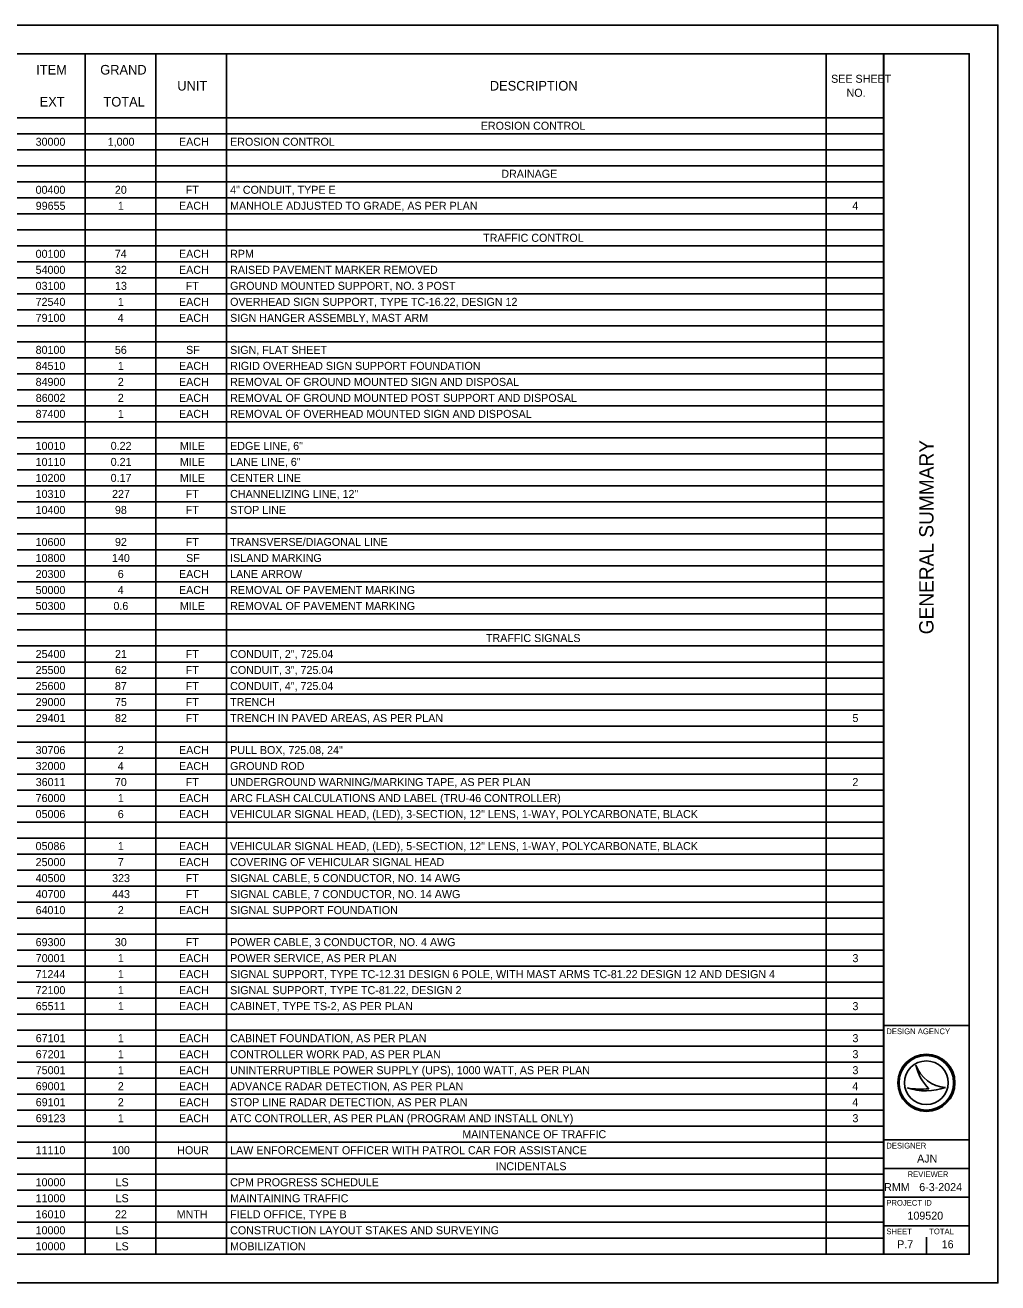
# Model space of a CAD drawing. Extents: x 0 to 34, y 0 to 22.
# Drawn here: x 16.99 to 34, y 0 to 22 of the extents above; entities that cross this region are included whole.
import ezdxf

# ---------------------------------------------------------------- set-up
doc = ezdxf.new("R2010")
doc.units = 0
for name, color, linetype in [('Default', 7, 'Continuous'), ('SH_Border', 7, 'Continuous'), ('SH_Cut_Line', 7, 'Continuous'), ('SH_Data', 7, 'Continuous')]:
    doc.layers.add(name, color=color, linetype=linetype)

msp = doc.modelspace()

# ---------------------------------------------------------------- linework, layer by layer
at = {"layer": 'Default'}
for p, q in [((1.5, 21.5), (32.004, 21.5)), ((18.036, 21.5), (18.036, 0.5)), ((19.272, 21.5), (19.272, 0.5)), ((20.507, 21.5), (20.507, 0.5)), ((30.999, 21.5), (30.999, 0.5)), ((32.004, 21.5), (32.004, 0.5)), ((1.5, 20.38), (32.004, 20.38)), ((1.5, 20.1), (32.004, 20.1)), ((1.5, 19.82), (32.004, 19.82)), ((1.5, 19.54), (32.004, 19.54)), ((1.5, 19.26), (32.004, 19.26)), ((1.5, 18.98), (32.004, 18.98)), ((1.5, 18.7), (32.004, 18.7)), ((1.5, 18.42), (32.004, 18.42)), ((1.5, 18.14), (32.004, 18.14)), ((1.5, 17.86), (32.004, 17.86)), ((1.5, 17.58), (32.004, 17.58)), ((1.5, 17.3), (32.004, 17.3)), ((1.5, 17.02), (32.004, 17.02)), ((1.5, 16.74), (32.004, 16.74)), ((1.5, 16.46), (32.004, 16.46)), ((1.5, 16.18), (32.004, 16.18)), ((1.5, 15.9), (32.004, 15.9)), ((1.5, 15.62), (32.004, 15.62)), ((1.5, 15.34), (32.004, 15.34)), ((1.5, 15.06), (32.004, 15.06)), ((1.5, 14.78), (32.004, 14.78)), ((1.5, 14.5), (32.004, 14.5)), ((1.5, 14.22), (32.004, 14.22)), ((1.5, 13.94), (32.004, 13.94)), ((1.5, 13.66), (32.004, 13.66)), ((1.5, 13.38), (32.004, 13.38)), ((1.5, 13.1), (32.004, 13.1)), ((1.5, 12.82), (32.004, 12.82)), ((1.5, 12.54), (32.004, 12.54)), ((1.5, 12.26), (32.004, 12.26)), ((1.5, 11.98), (32.004, 11.98)), ((1.5, 11.7), (32.004, 11.7)), ((1.5, 11.42), (32.004, 11.42)), ((1.5, 11.14), (32.004, 11.14)), ((1.5, 10.86), (32.004, 10.86)), ((1.5, 10.58), (32.004, 10.58)), ((1.5, 10.3), (32.004, 10.3)), ((1.5, 10.02), (32.004, 10.02)), ((1.5, 9.74), (32.004, 9.74)), ((1.5, 9.46), (32.004, 9.46)), ((1.5, 9.18), (32.004, 9.18)), ((1.5, 8.9), (32.004, 8.9)), ((1.5, 8.62), (32.004, 8.62)), ((1.5, 8.34), (32.004, 8.34)), ((1.5, 8.06), (32.004, 8.06)), ((1.5, 7.78), (32.004, 7.78)), ((1.5, 7.5), (32.004, 7.5)), ((1.5, 7.22), (32.004, 7.22)), ((1.5, 6.94), (32.004, 6.94)), ((1.5, 6.66), (32.004, 6.66)), ((1.5, 6.38), (32.004, 6.38)), ((1.5, 6.1), (32.004, 6.1)), ((1.5, 5.82), (32.004, 5.82)), ((1.5, 5.54), (32.004, 5.54)), ((1.5, 5.26), (32.004, 5.26)), ((1.5, 4.98), (32.004, 4.98)), ((1.5, 4.7), (32.004, 4.7)), ((1.5, 4.42), (32.004, 4.42)), ((1.5, 4.14), (32.004, 4.14)), ((1.5, 3.86), (32.004, 3.86)), ((1.5, 3.58), (32.004, 3.58)), ((1.5, 3.3), (32.004, 3.3)), ((1.5, 3.02), (32.004, 3.02)), ((1.5, 2.74), (32.004, 2.74)), ((1.5, 2.46), (32.004, 2.46)), ((1.5, 2.18), (32.004, 2.18)), ((1.5, 1.9), (32.004, 1.9)), ((1.5, 1.62), (32.004, 1.62)), ((1.5, 1.34), (32.004, 1.34)), ((1.5, 1.06), (32.004, 1.06)), ((1.5, 0.78), (32.004, 0.78)), ((1.5, 0.5), (32.004, 0.5))]:
    msp.add_line(p, q, dxfattribs=at)
at = {"layer": 'SH_Border'}
for p, q in [((32, 0.5), (32, 21.5)), ((32, 4.5), (33.5, 4.5)), ((32, 2.5), (33.5, 2.5)), ((32, 2), (33.5, 2)), ((32, 1.5), (33.5, 1.5)), ((32, 1), (33.5, 1))]:
    msp.add_line(p, q, dxfattribs=at)
msp.add_lwpolyline([(1.5, 21.5), (33.5, 21.5), (33.5, 0.5), (1.5, 0.5)], close=True, dxfattribs=at)
at = {"layer": 'SH_Cut_Line'}
msp.add_lwpolyline([(0, 0), (34, 0), (34, 22), (0, 22)], close=True, dxfattribs=at)
at = {"layer": 'SH_Data'}
for p, q in [((32.567, 3.81), (32.567, 3.81)), ((32.417, 3.41), (32.417, 3.41)), ((32.75, 3.5), (32.75, 3.5)), ((33.087, 3.419), (33.087, 3.419)), ((32.375, 0.675), (32.375, 0.675)), ((32.75, 0.5), (32.75, 0.8))]:
    msp.add_line(p, q, dxfattribs=at)
for radius in [0.5, 0.477, 0.477, 0.382]:
    msp.add_circle((32.75, 3.5), radius, dxfattribs=at)
for centre, radius, start, end in [((33.116, 3.998), 0.58, 198.9257, 198.9319), ((33.347, 3.97), 0.796, 191.6379, 191.6421), ((33.116, 3.998), 0.58, 198.9319, 267.1657), ((33.347, 3.97), 0.796, 191.6421, 226.0947), ((32.739, 4.37), 1.013, 251.4576, 290.0832), ((32.648, 4.654), 1.266, 259.4964, 259.4995), ((32.739, 4.37), 1.013, 251.4527, 251.4576), ((32.648, 4.654), 1.266, 259.4995, 276.6672)]:
    msp.add_arc(centre, radius, start, end, dxfattribs=at)

# ---------------------------------------------------------------- texts
at = {"layer": 'Default'}
for s, height, p in [('ITEM', 0.168, (17.181, 21.136)), ('GRAND', 0.168, (18.301, 21.136)), ('SEE SHEET ', 0.14, (31.084, 20.992)), ('UNIT', 0.168, (19.649, 20.856)), ('DESCRIPTION', 0.168, (25.115, 20.856)), ('EXT', 0.168, (17.242, 20.576)), ('TOTAL', 0.168, (18.357, 20.576)), ('NO.', 0.14, (31.354, 20.747)), ('EROSION CONTROL', 0.14, (24.957, 20.17)), ('30000', 0.14, (17.171, 19.89)), ('1,000', 0.14, (18.432, 19.89)), ('EACH', 0.14, (19.679, 19.89)), ('EROSION CONTROL', 0.14, (20.573, 19.89)), ('DRAINAGE', 0.14, (25.316, 19.33)), ('00400', 0.14, (17.171, 19.05)), ('20', 0.14, (18.557, 19.05)), ('FT', 0.14, (19.796, 19.05)), ('4" CONDUIT, TYPE E', 0.14, (20.573, 19.05)), ('99655', 0.14, (17.173, 18.77)), ('1', 0.14, (18.609, 18.77)), ('EACH', 0.14, (19.679, 18.77)), ('MANHOLE ADJUSTED TO GRADE, AS PER PLAN', 0.14, (20.573, 18.77)), ('4', 0.14, (31.454, 18.77)), ('TRAFFIC CONTROL', 0.14, (24.998, 18.21)), ('00100', 0.14, (17.171, 17.93)), ('74', 0.14, (18.556, 17.93)), ('EACH', 0.14, (19.679, 17.93)), ('RPM', 0.14, (20.573, 17.93)), ('54000', 0.14, (17.171, 17.65)), ('32', 0.14, (18.559, 17.65)), ('EACH', 0.14, (19.679, 17.65)), ('RAISED PAVEMENT MARKER REMOVED', 0.14, (20.573, 17.65)), ('03100', 0.14, (17.171, 17.37)), ('13', 0.14, (18.56, 17.37)), ('FT', 0.14, (19.796, 17.37)), ('GROUND MOUNTED SUPPORT, NO. 3 POST', 0.14, (20.573, 17.37)), ('72540', 0.14, (17.171, 17.09)), ('1', 0.14, (18.609, 17.09)), ('EACH', 0.14, (19.679, 17.09)), ('OVERHEAD SIGN SUPPORT, TYPE TC-16.22, DESIGN 12', 0.14, (20.573, 17.09)), ('79100', 0.14, (17.171, 16.81)), ('4', 0.14, (18.607, 16.81)), ('EACH', 0.14, (19.679, 16.81)), ('SIGN HANGER ASSEMBLY, MAST ARM', 0.14, (20.573, 16.81)), ('80100', 0.14, (17.171, 16.25)), ('56', 0.14, (18.557, 16.25)), ('SF', 0.14, (19.803, 16.25)), ('SIGN, FLAT SHEET', 0.14, (20.573, 16.25)), ('84510', 0.14, (17.171, 15.97)), ('1', 0.14, (18.609, 15.97)), ('EACH', 0.14, (19.679, 15.97)), ('RIGID OVERHEAD SIGN SUPPORT FOUNDATION', 0.14, (20.573, 15.97)), ('84900', 0.14, (17.171, 15.69)), ('2', 0.14, (18.609, 15.69)), ('EACH', 0.14, (19.679, 15.69)), ('REMOVAL OF GROUND MOUNTED SIGN AND DISPOSAL', 0.14, (20.573, 15.69)), ('86002', 0.14, (17.173, 15.41)), ('2', 0.14, (18.609, 15.41)), ('EACH', 0.14, (19.679, 15.41)), ('REMOVAL OF GROUND MOUNTED POST SUPPORT AND DISPOSAL', 0.14, (20.573, 15.41)), ('87400', 0.14, (17.171, 15.13)), ('1', 0.14, (18.609, 15.13)), ('EACH', 0.14, (19.679, 15.13)), ('REMOVAL OF OVERHEAD MOUNTED SIGN AND DISPOSAL', 0.14, (20.573, 15.13)), ('10010', 0.14, (17.171, 14.57)), ('0.22', 0.14, (18.484, 14.57)), ('MILE', 0.14, (19.695, 14.57)), ('EDGE LINE, 6"', 0.14, (20.573, 14.57)), ('10110', 0.14, (17.171, 14.29)), ('0.21', 0.14, (18.484, 14.29)), ('MILE', 0.14, (19.695, 14.29)), ('LANE LINE, 6"', 0.14, (20.573, 14.29)), ('10200', 0.14, (17.171, 14.01)), ('0.17', 0.14, (18.483, 14.01)), ('MILE', 0.14, (19.695, 14.01)), ('CENTER LINE', 0.14, (20.573, 14.01)), ('10310', 0.14, (17.171, 13.73)), ('227', 0.14, (18.508, 13.73)), ('FT', 0.14, (19.796, 13.73)), ('CHANNELIZING LINE, 12"', 0.14, (20.573, 13.73)), ('10400', 0.14, (17.171, 13.45)), ('98', 0.14, (18.558, 13.45)), ('FT', 0.14, (19.796, 13.45)), ('STOP LINE', 0.14, (20.573, 13.45)), ('10600', 0.14, (17.171, 12.89)), ('92', 0.14, (18.559, 12.89)), ('FT', 0.14, (19.796, 12.89)), ('TRANSVERSE/DIAGONAL LINE', 0.14, (20.573, 12.89)), ('10800', 0.14, (17.171, 12.61)), ('140', 0.14, (18.507, 12.61)), ('SF', 0.14, (19.803, 12.61)), ('ISLAND MARKING', 0.14, (20.573, 12.61)), ('20300', 0.14, (17.171, 12.33)), ('6', 0.14, (18.608, 12.33)), ('EACH', 0.14, (19.679, 12.33)), ('LANE ARROW', 0.14, (20.573, 12.33)), ('50000', 0.14, (17.171, 12.05)), ('4', 0.14, (18.607, 12.05)), ('EACH', 0.14, (19.679, 12.05)), ('REMOVAL OF PAVEMENT MARKING', 0.14, (20.573, 12.05)), ('50300', 0.14, (17.171, 11.77)), ('0.6', 0.14, (18.532, 11.77)), ('MILE', 0.14, (19.695, 11.77)), ('REMOVAL OF PAVEMENT MARKING', 0.14, (20.573, 11.77)), ('TRAFFIC SIGNALS', 0.14, (25.047, 11.21)), ('25400', 0.14, (17.171, 10.93)), ('21', 0.14, (18.559, 10.93)), ('FT', 0.14, (19.796, 10.93)), ('CONDUIT, 2", 725.04', 0.14, (20.573, 10.93)), ('25500', 0.14, (17.171, 10.65)), ('62', 0.14, (18.559, 10.65)), ('FT', 0.14, (19.796, 10.65)), ('CONDUIT, 3", 725.04', 0.14, (20.573, 10.65)), ('25600', 0.14, (17.171, 10.37)), ('87', 0.14, (18.558, 10.37)), ('FT', 0.14, (19.796, 10.37)), ('CONDUIT, 4", 725.04', 0.14, (20.573, 10.37)), ('29000', 0.14, (17.171, 10.09)), ('75', 0.14, (18.559, 10.09)), ('FT', 0.14, (19.796, 10.09)), ('TRENCH', 0.14, (20.573, 10.09)), ('29401', 0.14, (17.173, 9.81)), ('82', 0.14, (18.559, 9.81)), ('FT', 0.14, (19.796, 9.81)), ('TRENCH IN PAVED AREAS, AS PER PLAN', 0.14, (20.573, 9.81)), ('5', 0.14, (31.457, 9.81)), ('30706', 0.14, (17.171, 9.25)), ('2', 0.14, (18.609, 9.25)), ('EACH', 0.14, (19.679, 9.25)), ('PULL BOX, 725.08, 24"', 0.14, (20.573, 9.25)), ('32000', 0.14, (17.171, 8.97)), ('4', 0.14, (18.607, 8.97)), ('EACH', 0.14, (19.679, 8.97)), ('GROUND ROD', 0.14, (20.573, 8.97)), ('36011', 0.14, (17.173, 8.69)), ('70', 0.14, (18.557, 8.69)), ('FT', 0.14, (19.796, 8.69)), ('UNDERGROUND WARNING/MARKING TAPE, AS PER PLAN', 0.14, (20.573, 8.69)), ('2', 0.14, (31.456, 8.69)), ('76000', 0.14, (17.171, 8.41)), ('1', 0.14, (18.609, 8.41)), ('EACH', 0.14, (19.679, 8.41)), ('ARC FLASH CALCULATIONS AND LABEL (TRU-46 CONTROLLER)', 0.14, (20.573, 8.41)), ('05006', 0.14, (17.171, 8.13)), ('6', 0.14, (18.608, 8.13)), ('EACH', 0.14, (19.679, 8.13)), ('VEHICULAR SIGNAL HEAD, (LED), 3-SECTION, 12" LENS, 1-WAY, POLYCARBONATE, BLACK', 0.14, (20.573, 8.13)), ('05086', 0.14, (17.171, 7.57)), ('1', 0.14, (18.609, 7.57)), ('EACH', 0.14, (19.679, 7.57)), ('VEHICULAR SIGNAL HEAD, (LED), 5-SECTION, 12" LENS, 1-WAY, POLYCARBONATE, BLACK', 0.14, (20.573, 7.57)), ('25000', 0.14, (17.171, 7.29)), ('7', 0.14, (18.608, 7.29)), ('EACH', 0.14, (19.679, 7.29)), ('COVERING OF VEHICULAR SIGNAL HEAD', 0.14, (20.573, 7.29)), ('40500', 0.14, (17.171, 7.01)), ('323', 0.14, (18.509, 7.01)), ('FT', 0.14, (19.796, 7.01)), ('SIGNAL CABLE, 5 CONDUCTOR, NO. 14 AWG', 0.14, (20.573, 7.01)), ('40700', 0.14, (17.171, 6.73)), ('443', 0.14, (18.509, 6.73)), ('FT', 0.14, (19.796, 6.73)), ('SIGNAL CABLE, 7 CONDUCTOR, NO. 14 AWG', 0.14, (20.573, 6.73)), ('64010', 0.14, (17.171, 6.45)), ('2', 0.14, (18.609, 6.45)), ('EACH', 0.14, (19.679, 6.45)), ('SIGNAL SUPPORT FOUNDATION', 0.14, (20.573, 6.45)), ('69300', 0.14, (17.171, 5.89)), ('30', 0.14, (18.557, 5.89)), ('FT', 0.14, (19.796, 5.89)), ('POWER CABLE, 3 CONDUCTOR, NO. 4 AWG', 0.14, (20.573, 5.89)), ('70001', 0.14, (17.173, 5.61)), ('1', 0.14, (18.609, 5.61)), ('EACH', 0.14, (19.679, 5.61)), ('POWER SERVICE, AS PER PLAN', 0.14, (20.573, 5.61)), ('3', 0.14, (31.457, 5.61)), ('71244', 0.14, (17.17, 5.33)), ('1', 0.14, (18.609, 5.33)), ('EACH', 0.14, (19.679, 5.33)), ('SIGNAL SUPPORT, TYPE TC-12.31 DESIGN 6 POLE, WITH MAST ARMS TC-81.22 DESIGN 12 AND DESIGN 4', 0.14, (20.573, 5.33)), ('72100', 0.14, (17.171, 5.05)), ('1', 0.14, (18.609, 5.05)), ('EACH', 0.14, (19.679, 5.05)), ('SIGNAL SUPPORT, TYPE TC-81.22, DESIGN 2', 0.14, (20.573, 5.05)), ('65511', 0.14, (17.173, 4.77)), ('1', 0.14, (18.609, 4.77)), ('EACH', 0.14, (19.679, 4.77)), ('CABINET, TYPE TS-2, AS PER PLAN', 0.14, (20.573, 4.77)), ('3', 0.14, (31.457, 4.77)), ('67101', 0.14, (17.173, 4.21)), ('1', 0.14, (18.609, 4.21)), ('EACH', 0.14, (19.679, 4.21)), ('CABINET FOUNDATION, AS PER PLAN', 0.14, (20.573, 4.21)), ('3', 0.14, (31.457, 4.21)), ('67201', 0.14, (17.173, 3.93)), ('1', 0.14, (18.609, 3.93)), ('EACH', 0.14, (19.679, 3.93)), ('CONTROLLER WORK PAD, AS PER PLAN', 0.14, (20.573, 3.93)), ('3', 0.14, (31.457, 3.93)), ('75001', 0.14, (17.173, 3.65)), ('1', 0.14, (18.609, 3.65)), ('EACH', 0.14, (19.679, 3.65)), ('UNINTERRUPTIBLE POWER SUPPLY (UPS), 1000 WATT, AS PER PLAN', 0.14, (20.573, 3.65)), ('3', 0.14, (31.457, 3.65)), ('69001', 0.14, (17.173, 3.37)), ('2', 0.14, (18.609, 3.37)), ('EACH', 0.14, (19.679, 3.37)), ('ADVANCE RADAR DETECTION, AS PER PLAN', 0.14, (20.573, 3.37)), ('4', 0.14, (31.454, 3.37)), ('69101', 0.14, (17.173, 3.09)), ('2', 0.14, (18.609, 3.09)), ('EACH', 0.14, (19.679, 3.09)), ('STOP LINE RADAR DETECTION, AS PER PLAN', 0.14, (20.573, 3.09)), ('4', 0.14, (31.454, 3.09)), ('69123', 0.14, (17.173, 2.81)), ('1', 0.14, (18.609, 2.81)), ('EACH', 0.14, (19.679, 2.81)), ('ATC CONTROLLER, AS PER PLAN (PROGRAM AND INSTALL ONLY)', 0.14, (20.573, 2.81)), ('3', 0.14, (31.457, 2.81)), ('MAINTENANCE OF TRAFFIC', 0.14, (24.634, 2.53)), ('11110', 0.14, (17.171, 2.25)), ('100', 0.14, (18.507, 2.25)), ('HOUR', 0.14, (19.648, 2.25)), ('LAW ENFORCEMENT OFFICER WITH PATROL CAR FOR ASSISTANCE', 0.14, (20.573, 2.25)), ('INCIDENTALS', 0.14, (25.218, 1.97)), ('10000', 0.14, (17.171, 1.69)), ('LS', 0.14, (18.57, 1.69)), ('CPM PROGRESS SCHEDULE', 0.14, (20.573, 1.69)), ('11000', 0.14, (17.171, 1.41)), ('LS', 0.14, (18.57, 1.41)), ('MAINTAINING TRAFFIC', 0.14, (20.573, 1.41)), ('16010', 0.14, (17.171, 1.13)), ('22', 0.14, (18.559, 1.13)), ('MNTH', 0.14, (19.639, 1.13)), ('FIELD OFFICE, TYPE B', 0.14, (20.573, 1.13)), ('10000', 0.14, (17.171, 0.85)), ('LS', 0.14, (18.57, 0.85)), ('CONSTRUCTION LAYOUT STAKES AND SURVEYING', 0.14, (20.573, 0.85)), ('10000', 0.14, (17.171, 0.57)), ('LS', 0.14, (18.57, 0.57)), ('MOBILIZATION', 0.14, (20.573, 0.57))]:
    msp.add_text(s, height=height, dxfattribs=at).set_placement(p)
at = {"layer": 'SH_Data'}
msp.add_text('GENERAL SUMMARY', height=0.25, rotation=90, dxfattribs=at).set_placement((32.875, 11.344))
for s, height, p in [('DESIGN AGENCY', 0.1, (32.05, 4.35)), ('DESIGNER', 0.1, (32.05, 2.35)), ('AJN', 0.14, (32.588, 2.105)), ('REVIEWER', 0.1, (32.422, 1.85)), ('RMM', 0.14, (32.011, 1.605)), ('6-3-2024', 0.14, (32.625, 1.605)), ('PROJECT ID', 0.1, (32.05, 1.35)), ('109520', 0.14, (32.419, 1.105)), ('SHEET', 0.1, (32.05, 0.85)), ('TOTAL', 0.1, (32.8, 0.85)), ('P.7', 0.14, (32.239, 0.605)), ('16', 0.14, (33.018, 0.605))]:
    msp.add_text(s, height=height, dxfattribs=at).set_placement(p)

doc.saveas('drawing.dxf')
